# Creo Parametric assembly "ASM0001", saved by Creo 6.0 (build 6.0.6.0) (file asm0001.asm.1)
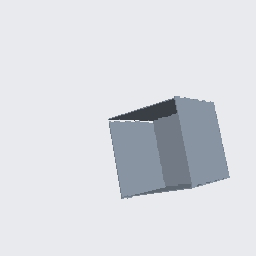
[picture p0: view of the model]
Units: Inch lbm Second (Pro/E Default); INCH, POUND, SECS

Created from: INLBS_ASM_DESIGN.ASM

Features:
  1. datum plane "ASM_RIGHT"
  2. datum plane "ASM_TOP"
  3. datum plane "ASM_FRONT"
  4. coordinate system
  5. component "PRT0001"
  6. coordinate system
  7. component "RIGHT"
  8. coordinate system
  9. component "PRT0002"
  10. component "LEFT"
  11. coordinate system
  12. component "BACK"

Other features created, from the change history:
  component "BACK.PRT"

Other named items: ACS2, ACS3, ACS4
